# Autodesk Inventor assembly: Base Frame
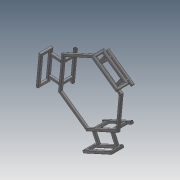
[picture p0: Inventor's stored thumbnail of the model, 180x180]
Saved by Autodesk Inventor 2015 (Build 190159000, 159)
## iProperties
Created: 2015-05
Part Number: Base Frame
Document SubType Name: Assembly
Designer: TREINA6
_SolveAssemblyDoc: Frame Generator Solve Assembly
_Version: 15.0.0
Author: TREINA6
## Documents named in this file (3)
- C:\Users\TREINA6\Desktop\#46- Sheet Metal Technology\WSC2015_TP46_pre\Sheet Metal\Base Assembly\Base Frame\Base Frame.iam
- C:\Users\TREINA6\Desktop\#46- Sheet Metal Technology\WSC2015_TP46_pre\Sheet Metal\Base Assembly\Base Frame\Skeleton.ipt
- C:\Users\TREINA6\Desktop\#46- Sheet Metal Technology\WSC2015_TP46_pre\Sheet Metal\Base Assembly\Base Frame\Base Frame\Frame\Frame0001.iam
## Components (2 placed, 2 different names)
1. Skeleton:1 — Mate:1
2. Frame0001:1 [sub-assembly]
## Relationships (1: Mate 1)
- Mate:1: Skeleton:1
